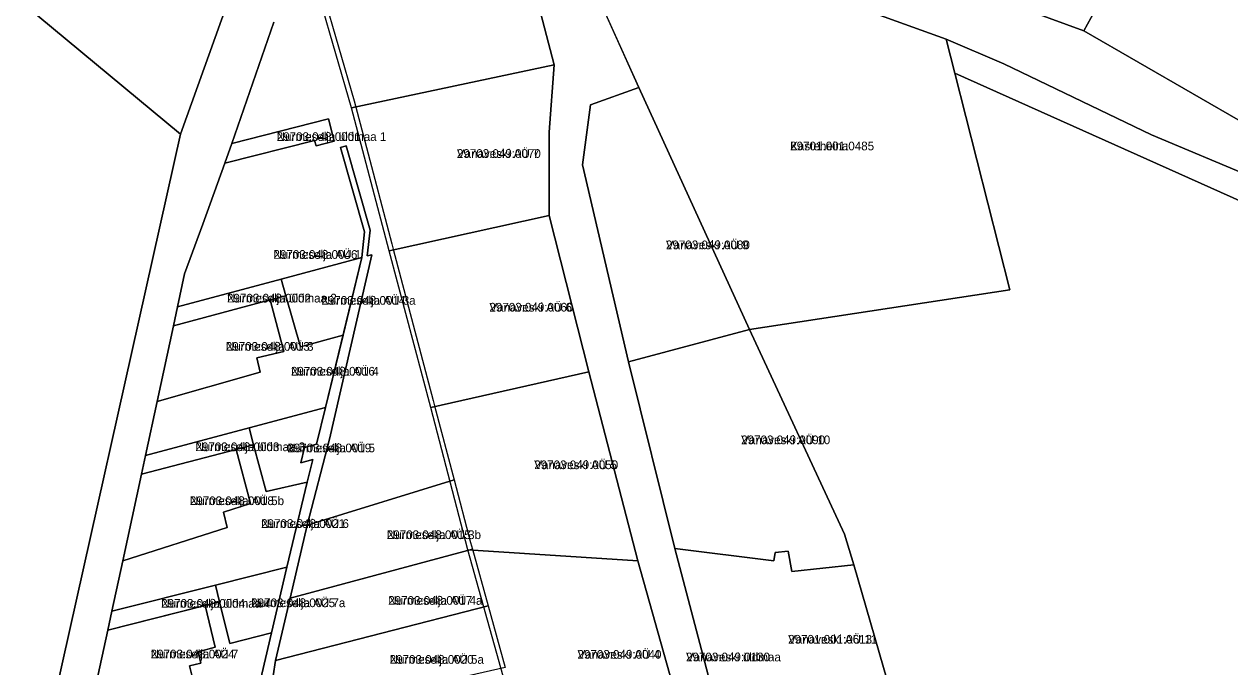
# Model space of a CAD drawing. Extents: x 504287 to 537970, y 6539941 to 6586214.
# Drawn here: x 520302.7 to 520511, y 6560725.1 to 6560836.1 of the extents above; entities that cross this region are included whole.
import ezdxf

# ---------------------------------------------------------------- set-up
doc = ezdxf.new("R2010")
doc.units = 0
for name, color, linetype in [('L_AADRESS', 7, 'Continuous'), ('PIIR', 7, 'Continuous'), ('TUNNUS', 7, 'Continuous')]:
    doc.layers.add(name, color=color, linetype=linetype)

msp = doc.modelspace()

# ---------------------------------------------------------------- linework, layer by layer
at = {"layer": 'PIIR'}
for points in [[(520823.52, 6560789.51), (520809.49, 6560778.92), (520790.49, 6560768.78), (520776.29, 6560762.8), (520745.63, 6560751.85), (520725.29, 6560740.74), (520676.73, 6560765.63), (520602.05, 6560793.24), (520543.83, 6560809.29), (520568.43, 6560875.43), (520519.97, 6560897.18), (520485.77, 6560834.97), (520416.43, 6560860.32), (520396.33, 6560904.53), (520382.01, 6560924.6), (520469.8, 6560976.54), (520696.24, 6561130.56), (520788.6, 6561063.86), (520853.16, 6561351.92)], [(520416.43, 6560860.32), (520485.77, 6560834.97), (520513.96, 6560818.72), (520543.83, 6560809.29), (520602.05, 6560793.24), (520676.73, 6560765.63), (520725.29, 6560740.74), (520722.99, 6560728.67), (520721.08, 6560731.3), (520717.77, 6560734.11), (520711.54, 6560738.33), (520702.58, 6560743.88), (520693.52, 6560748.75), (520683.08, 6560753.72), (520642.85, 6560768.08), (520606.24, 6560781.9), (520573.82, 6560792.59), (520533.34, 6560803.66), (520515.05, 6560809.62), (520497.45, 6560817), (520471.94, 6560829.23), (520462.01, 6560833.52), (520442.63, 6560840.55)], [(520345.85, 6560836.45), (520338.58, 6560815.5), (520337.38, 6560812.1), (520333.54, 6560801.52), (520330.42, 6560792.95), (520329.2, 6560787.29), (520328.48, 6560783.98), (520325.66, 6560770.91), (520323.65, 6560761.6), (520322.95, 6560758.34), (520319.72, 6560743.4), (520317.84, 6560734.71), (520317.13, 6560731.4), (520314.1, 6560717.42), (520313.46, 6560714.39), (520312.15, 6560708.54), (520304.57, 6560704.46), (520329.71, 6560817.12), (520338.67, 6560842.22)], [(520354.29, 6560841.58), (520359.7, 6560822.86), (520361.54, 6560815.88), (520366.21, 6560798.17), (520366.46, 6560797.23), (520373.36, 6560771.1), (520373.61, 6560770.15), (520376.99, 6560757.36), (520351.6, 6560749.54), (520355.48, 6560764.39), (520362.79, 6560796.25), (520361.99, 6560796.06), (520362.47, 6560800.49), (520358.35, 6560815.05), (520357.38, 6560814.77), (520361.51, 6560800.22), (520361.03, 6560795.79), (520347.08, 6560792.06), (520329.2, 6560787.29), (520330.42, 6560792.95), (520333.54, 6560801.52), (520337.38, 6560812.1), (520352.86, 6560816.02), (520353.13, 6560815.06), (520356.28, 6560815.86), (520355.3, 6560819.73), (520338.58, 6560815.5), (520345.85, 6560836.45)], [(520302.69, 6560839.49), (520329.71, 6560817.12), (520304.57, 6560704.46), (520355.32, 6560620.09), (520363.31, 6560606.8), (520366.18, 6560602.04), (520370.44, 6560600.22), (520374.2, 6560601.62), (520392.82, 6560609.1), (520393.97, 6560609.56), (520414.9, 6560617.97), (520442.74, 6560629.04), (520447.43, 6560630.97), (520474.34, 6560641.23), (520489, 6560648.42), (520470.87, 6560478)], [(520513.23, 6560805.33), (520463.5, 6560827.64), (520462.01, 6560833.52), (520471.94, 6560829.23), (520497.45, 6560817), (520515.05, 6560809.62)], [(520341.93, 6560715.94), (520345.45, 6560730.93), (520348.11, 6560742.29), (520351.61, 6560756.95), (520352.58, 6560760.89), (520350.49, 6560760.34), (520351.14, 6560762.99), (520353.23, 6560763.54), (520354.77, 6560769.85), (520361.03, 6560795.79), (520361.51, 6560800.22), (520357.38, 6560814.77), (520358.35, 6560815.05), (520362.47, 6560800.49), (520361.99, 6560796.06), (520362.79, 6560796.25), (520355.48, 6560764.39), (520351.6, 6560749.54), (520348.64, 6560736.95), (520346.12, 6560726.18), (520344.5, 6560715.6)]]:
    msp.add_lwpolyline(points, dxfattribs=at)
for points in [[(520519.97, 6560897.18), (520568.43, 6560875.43), (520543.83, 6560809.29), (520513.96, 6560818.72), (520485.77, 6560834.97)], [(520338.67, 6560842.22), (520329.71, 6560817.12), (520302.69, 6560839.49), (520324.82, 6560866.27), (520342.03, 6560843.84)], [(520393.39, 6560817.41), (520394.25, 6560829.05), (520387.32, 6560855.76), (520391.77, 6560857.58), (520394.38, 6560856.58), (520397.17, 6560851.16), (520408.91, 6560825.15), (520400.55, 6560822.16), (520399.14, 6560811.81), (520407.14, 6560777.78), (520415.14, 6560745.5), (520423.75, 6560712.68), (520430.87, 6560685.78), (520438.14, 6560657.98), (520446.79, 6560629.73), (520442.1, 6560627.8), (520432.98, 6560656.13), (520425.4, 6560684.17), (520417.22, 6560713.28), (520408.73, 6560743.38), (520400.25, 6560776.05), (520393.4, 6560803.05)], [(520353.84, 6560840.37), (520387.32, 6560855.76), (520394.25, 6560829.05), (520359.25, 6560821.65)], [(520408.91, 6560825.15), (520397.13, 6560851.29), (520407.9, 6560853.66), (520418.67, 6560851.17), (520429.08, 6560847.01), (520442.63, 6560840.55), (520462.01, 6560833.52), (520463.5, 6560827.64), (520472.98, 6560790.22), (520428.02, 6560783.37)], [(520359.25, 6560821.65), (520394.25, 6560829.05), (520393.39, 6560817.41), (520393.4, 6560803.05), (520365.77, 6560796.95)], [(520472.98, 6560790.22), (520463.5, 6560827.64), (520513.23, 6560805.33), (520531.76, 6560798.85), (520572.54, 6560787.8), (520604.8, 6560777.28), (520681.07, 6560749.09), (520700, 6560739.6), (520709.62, 6560732.32), (520680.7, 6560715.22), (520623.92, 6560690.86), (520590.57, 6560668.31), (520554.21, 6560636.97), (520489, 6560648.42), (520474.34, 6560641.23), (520467.21, 6560666.19), (520460.01, 6560692.95), (520452.54, 6560720.21), (520446.02, 6560742.67), (520444.43, 6560748), (520428.02, 6560783.37)], [(520399.14, 6560811.81), (520400.55, 6560822.16), (520408.91, 6560825.15), (520428.02, 6560783.37), (520407.14, 6560777.78)], [(520355.3, 6560819.73), (520356.28, 6560815.86), (520353.13, 6560815.06), (520352.86, 6560816.02), (520337.38, 6560812.1), (520338.58, 6560815.5)], [(520372.94, 6560769.85), (520365.77, 6560796.95), (520393.4, 6560803.05), (520400.25, 6560776.05)], [(520347.89, 6560789.17), (520347.08, 6560792.06), (520361.03, 6560795.79), (520357.79, 6560782.36), (520350.46, 6560780.36)], [(520347.08, 6560792.06), (520347.89, 6560789.17), (520345.18, 6560788.45), (520328.48, 6560783.98), (520329.2, 6560787.29)], [(520325.66, 6560770.91), (520343.5, 6560775.96), (520342.87, 6560778.46), (520347.55, 6560779.56), (520345.18, 6560788.45), (520347.89, 6560789.17), (520350.46, 6560780.36), (520357.79, 6560782.36), (520354.77, 6560769.85), (520341.55, 6560766.34), (520323.65, 6560761.6)], [(520328.48, 6560783.98), (520345.18, 6560788.45), (520347.55, 6560779.56), (520342.87, 6560778.46), (520343.5, 6560775.96), (520325.66, 6560770.91)], [(520407.14, 6560777.78), (520428.02, 6560783.37), (520444.43, 6560748), (520446.02, 6560742.67), (520435.31, 6560741.57), (520434.72, 6560745.06), (520432.45, 6560744.82), (520432.22, 6560743.39), (520415.14, 6560745.5)], [(520372.94, 6560769.85), (520400.25, 6560776.05), (520408.73, 6560743.38), (520379.38, 6560745.31)], [(520342.32, 6560763.44), (520341.55, 6560766.34), (520354.77, 6560769.85), (520353.23, 6560763.54), (520351.14, 6560762.99), (520350.49, 6560760.34), (520352.58, 6560760.89), (520351.61, 6560756.95), (520344.53, 6560755.39)], [(520341.55, 6560766.34), (520342.32, 6560763.44), (520339.31, 6560762.65), (520322.95, 6560758.34), (520323.65, 6560761.6)], [(520319.72, 6560743.4), (520337.79, 6560749.15), (520337.12, 6560751.82), (520341.78, 6560753.32), (520339.31, 6560762.65), (520342.32, 6560763.44), (520344.53, 6560755.39), (520351.61, 6560756.95), (520348.11, 6560742.29), (520335.73, 6560739.19), (520317.84, 6560734.71)], [(520322.95, 6560758.34), (520339.31, 6560762.65), (520341.78, 6560753.32), (520337.12, 6560751.82), (520337.79, 6560749.15), (520319.72, 6560743.4)], [(520351.6, 6560749.54), (520376.99, 6560757.36), (520379.83, 6560746.57), (520380.14, 6560745.42), (520348.64, 6560736.95)], [(520348.64, 6560736.95), (520380.14, 6560745.42), (520382.88, 6560735.61), (520346.12, 6560726.18)], [(520390.06, 6560706.99), (520379.38, 6560745.31), (520408.73, 6560743.38), (520417.22, 6560713.28)], [(520423.75, 6560712.68), (520415.14, 6560745.5), (520432.22, 6560743.39), (520432.45, 6560744.82), (520434.72, 6560745.06), (520435.31, 6560741.57), (520446.02, 6560742.67), (520452.54, 6560720.21)], [(520336.46, 6560736.28), (520335.73, 6560739.19), (520348.11, 6560742.29), (520345.45, 6560730.93), (520338.25, 6560729.1)], [(520335.73, 6560739.19), (520336.46, 6560736.28), (520317.13, 6560731.4), (520317.84, 6560734.71)], [(520318.93, 6560714.34), (520313.46, 6560714.39), (520314.1, 6560717.42), (520332.34, 6560720.87), (520331.26, 6560725.25), (520333.21, 6560725.72), (520332.74, 6560727.68), (520335.7, 6560728.45), (520333.99, 6560735.66), (520336.46, 6560736.28), (520338.25, 6560729.1), (520345.45, 6560730.93), (520341.93, 6560715.94), (520343.43, 6560711.52), (520334.07, 6560709.1), (520321.11, 6560705.77)], [(520335.7, 6560728.45), (520332.74, 6560727.68), (520333.21, 6560725.72), (520331.26, 6560725.25), (520332.34, 6560720.87), (520314.1, 6560717.42), (520317.13, 6560731.4), (520333.99, 6560735.66)], [(520346.12, 6560726.18), (520382.88, 6560735.61), (520385.83, 6560724.99), (520344.5, 6560715.6)]]:
    msp.add_lwpolyline(points, close=True, dxfattribs=at)

# ---------------------------------------------------------------- texts
at = {"layer": 'L_AADRESS'}
for s, p in [('Nurmeselja üldmaa 1', (520346.33, 6560815.92)), ('Kasteheina', (520435.05, 6560814.3)), ('Vanaveski AÜ 7', (520377.46, 6560813)), ('Vanaveski AÜ 9', (520413.58, 6560797.22)), ('Nurmeselja AÜ 1', (520345.77, 6560795.56)), ('Nurmeselja üldmaa 2', (520337.75, 6560788.02)), ('Nurmeselja AÜ 3a', (520354.05, 6560787.63)), ('Vanaveski AÜ 6', (520383.08, 6560786.45)), ('Nurmeselja AÜ 3', (520337.54, 6560779.68)), ('Nurmeselja AÜ 4', (520348.79, 6560775.39)), ('Nurmeselja üldmaa 3', (520332.29, 6560762.34)), ('Nurmeselja AÜ 5', (520348.16, 6560762.14)), ('Vanaveski AÜ 10', (520426.58, 6560763.54)), ('Vanaveski AÜ 5', (520390.83, 6560759.23)), ('Nurmeselja AÜ 5b', (520331.33, 6560753.02)), ('Nurmeselja AÜ 6', (520343.64, 6560749.08)), ('Nurmeselja AÜ 3b', (520365.36, 6560747.15)), ('Nurmeselja üldmaa 4', (520326.37, 6560735.29)), ('Nurmeselja AÜ 7a', (520341.92, 6560735.39)), ('Nurmeselja AÜ 4a', (520365.6, 6560735.8)), ('Vanaveski AÜ 11', (520434.7, 6560729.09)), ('Nurmeselja AÜ 7', (520324.55, 6560726.54)), ('Vanaveski AÜ 4', (520398.3, 6560726.48)), ('Nurmeselja AÜ 5a', (520365.85, 6560725.61)), ('Vanaveski üldmaa', (520417.05, 6560726.03))]:
    msp.add_text(s, height=1.5, dxfattribs=at).set_placement(p)
at = {"layer": 'TUNNUS'}
for s, p in [('29703:048:0001', (520346.33, 6560815.92)), ('29701:001:0485', (520435.05, 6560814.3)), ('29703:049:0070', (520377.46, 6560813)), ('29703:048:0046', (520345.77, 6560795.56)), ('29703:049:0080', (520413.58, 6560797.22)), ('29703:048:0002', (520337.75, 6560788.02)), ('29703:048:0014', (520354.05, 6560787.63)), ('29703:049:0060', (520383.08, 6560786.45)), ('29703:048:0013', (520337.54, 6560779.68)), ('29703:048:0016', (520348.79, 6560775.39)), ('29703:048:0003', (520332.29, 6560762.34)), ('29703:048:0019', (520348.16, 6560762.14)), ('29703:049:0090', (520426.58, 6560763.54)), ('29703:049:0050', (520390.83, 6560759.23)), ('29703:048:0018', (520331.33, 6560753.02)), ('29703:048:0021', (520343.64, 6560749.08)), ('29703:048:0015', (520365.36, 6560747.15)), ('29703:048:0004', (520326.37, 6560735.29)), ('29703:048:0025', (520341.92, 6560735.39)), ('29703:048:0017', (520365.6, 6560735.8)), ('29701:001:0613', (520434.7, 6560729.09)), ('29703:048:0024', (520324.55, 6560726.54)), ('29703:049:0040', (520398.3, 6560726.48)), ('29703:048:0020', (520365.85, 6560725.61)), ('29703:049:0130', (520417.05, 6560726.03))]:
    msp.add_text(s, height=1.5, dxfattribs=at).set_placement(p)

doc.saveas('drawing.dxf')
